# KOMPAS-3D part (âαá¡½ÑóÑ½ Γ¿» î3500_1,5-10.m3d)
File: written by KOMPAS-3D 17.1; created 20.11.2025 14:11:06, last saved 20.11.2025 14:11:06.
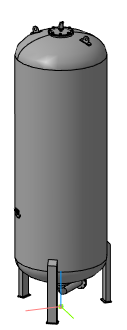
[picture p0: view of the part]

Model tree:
1. Операция без истории:1

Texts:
  REVIT MATERIAL OVERRIDDEN
  REVIT MATERIAL ID
  REVIT SUBCATEGORY ID
  REVIT CATEGORY ID
  REVIT ELEMENT ID
  REVIT BREP TAG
